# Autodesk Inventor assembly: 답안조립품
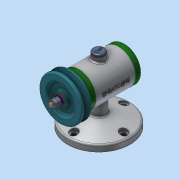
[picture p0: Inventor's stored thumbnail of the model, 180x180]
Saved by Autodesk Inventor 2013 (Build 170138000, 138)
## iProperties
Created: 2018-12
Part Number: 답안조립품
Document SubType Name: Assembly
Designer: Administrator
Author: Administrator
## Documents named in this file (15)
- C:\Users\Administrator\Desktop\481207V1008\답안조립품.iam
- C:\Users\Administrator\Desktop\481207V1008\본체.ipt
- C:\Users\Administrator\Desktop\481207V1008\V벨트풀리.ipt
- C:\Users\Administrator\Desktop\481207V1008\고무캡.ipt
- C:\Users\Administrator\Desktop\481207V1008\너트 M8.ipt
- 너트 M8.ipt
- C:\Users\Administrator\Desktop\481207V1008\뒤커버.ipt
- C:\Users\Administrator\Desktop\481207V1008\베어링 15 x 32 x 9.ipt
- C:\Users\Administrator\Desktop\481207V1008\볼트 M4 x 12.ipt
- C:\Users\Administrator\Desktop\481207V1008\스프링와셔 8.ipt
- C:\Users\Administrator\Desktop\481207V1008\앞커버.ipt
- C:\Users\Administrator\Desktop\481207V1008\오일 실 15 25 7.ipt
- C:\Users\Administrator\Desktop\481207V1008\와셔 8x17.ipt
- C:\Users\Administrator\Desktop\481207V1008\축.ipt
- C:\Users\Administrator\Desktop\481207V1008\키 3 x 3 x 12.ipt
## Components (2 placed, 2 different names)
1. V벨트풀리:1
2. 고무캡:1
